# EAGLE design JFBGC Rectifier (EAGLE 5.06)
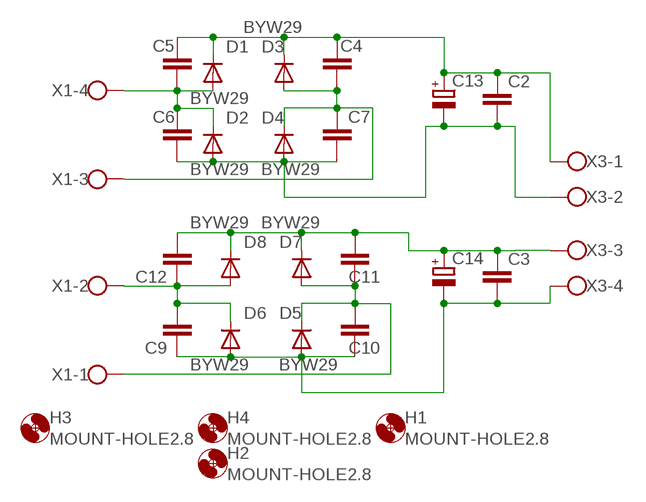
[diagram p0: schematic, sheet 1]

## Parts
C2  C5/3  [C5B3]
C3  C5/3  [C5B3]
C4  C5/3  [C5B3]
C5  C5/3  [C5B3]
C6  C5/3  [C5B3]
C7  C5/3  [C5B3]
C9  C5/3  [C5B3]
C10  C5/3  [C5B3]
C11  C5/3  [C5B3]
C12  C5/3  [C5B3]
C13  CPOL-EUE10-35  [EB35D]
C14  CPOL-EUE10-35  [EB35D]
D1  BYW29  [DO220S]
D2  BYW29  [DO220S]
D3  BYW29  [DO220S]
D4  BYW29  [DO220S]
D5  BYW29  [DO220S]
D6  BYW29  [DO220S]
D7  BYW29  [DO220S]
D8  BYW29  [DO220S]
H1  MOUNT-HOLE2.8  [2,8]
H2  MOUNT-HOLE2.8  [2,8]
H3  MOUNT-HOLE2.8  [2,8]
H4  MOUNT-HOLE2.8  [2,8]
X1  W237-4  [W237-4]
X3  W237-4  [W237-4]

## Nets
N$1: C2.2 C6.2 C7.2 C13.- D2.A D4.A X3.2
N$2: C2.1 C4.2 C5.1 C13.+ D1.C D3.C X3.1
N$3: C5.2 C6.1 D1.A D2.C X1.4
N$4: C3.1 C11.2 C12.2 C14.+ D7.C D8.C X3.3
N$9: C4.1 C7.1 D3.A D4.C X1.3
N$12: C3.2 C9.1 C10.1 C14.- D5.A D6.A X3.4
N$13: C9.2 C12.1 D6.C D8.A X1.2
N$15: C10.2 C11.1 D5.C D7.A X1.1

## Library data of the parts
C2-C7 C9-C12 = capacitor-wima:C: CAPACITOR
C13 C14 = rcl:CPOL-EU: POLARIZED CAPACITOR, European symbol
D1-D8 = diode:BYW29: DIODE
H1-H4 = holes:MOUNT-HOLE: MOUNTING HOLE with drill center marker
X1 X3 = con-wago-500:W237-4: WAGO SCREW CLAMP

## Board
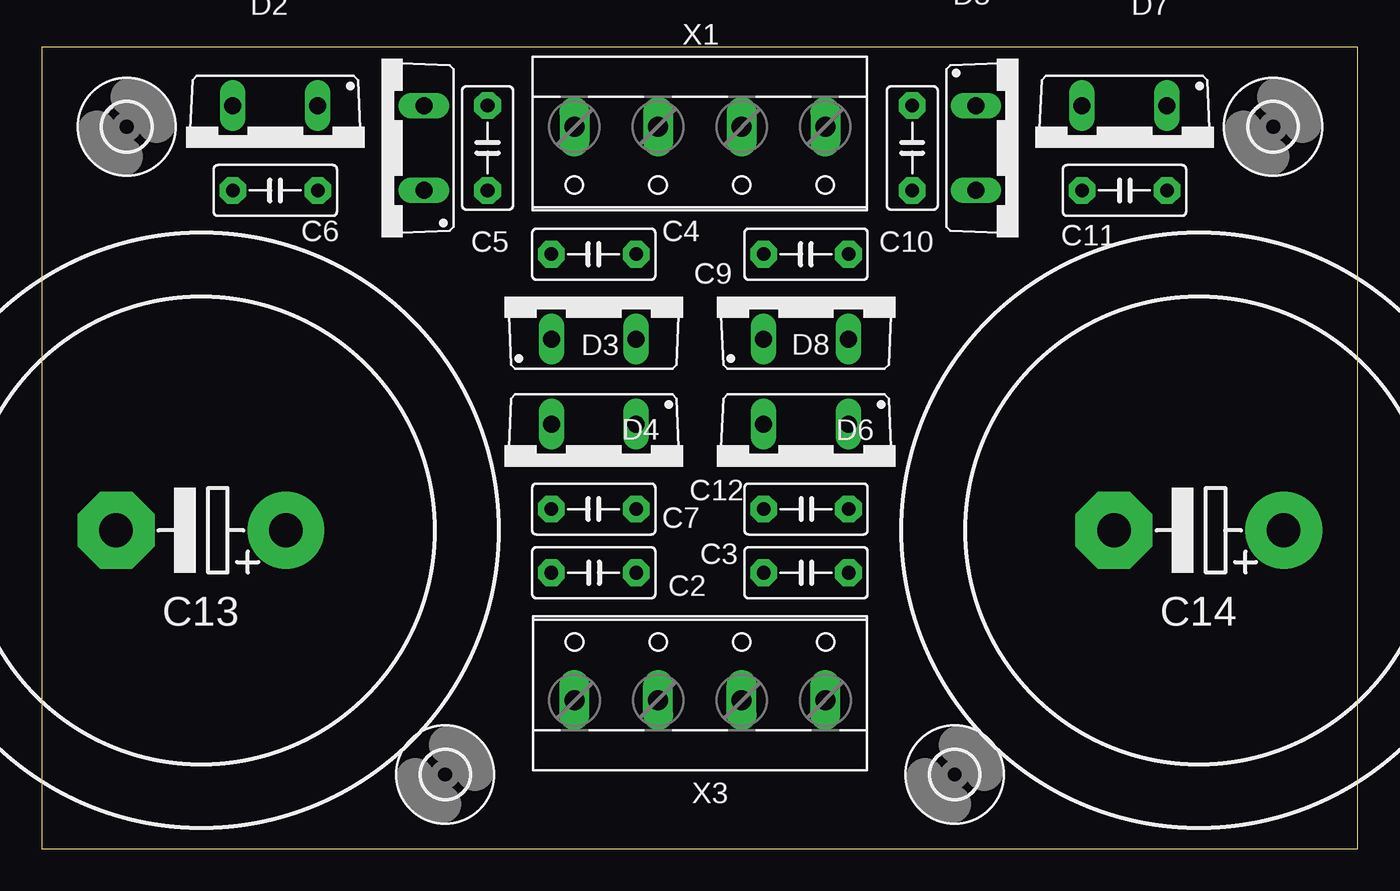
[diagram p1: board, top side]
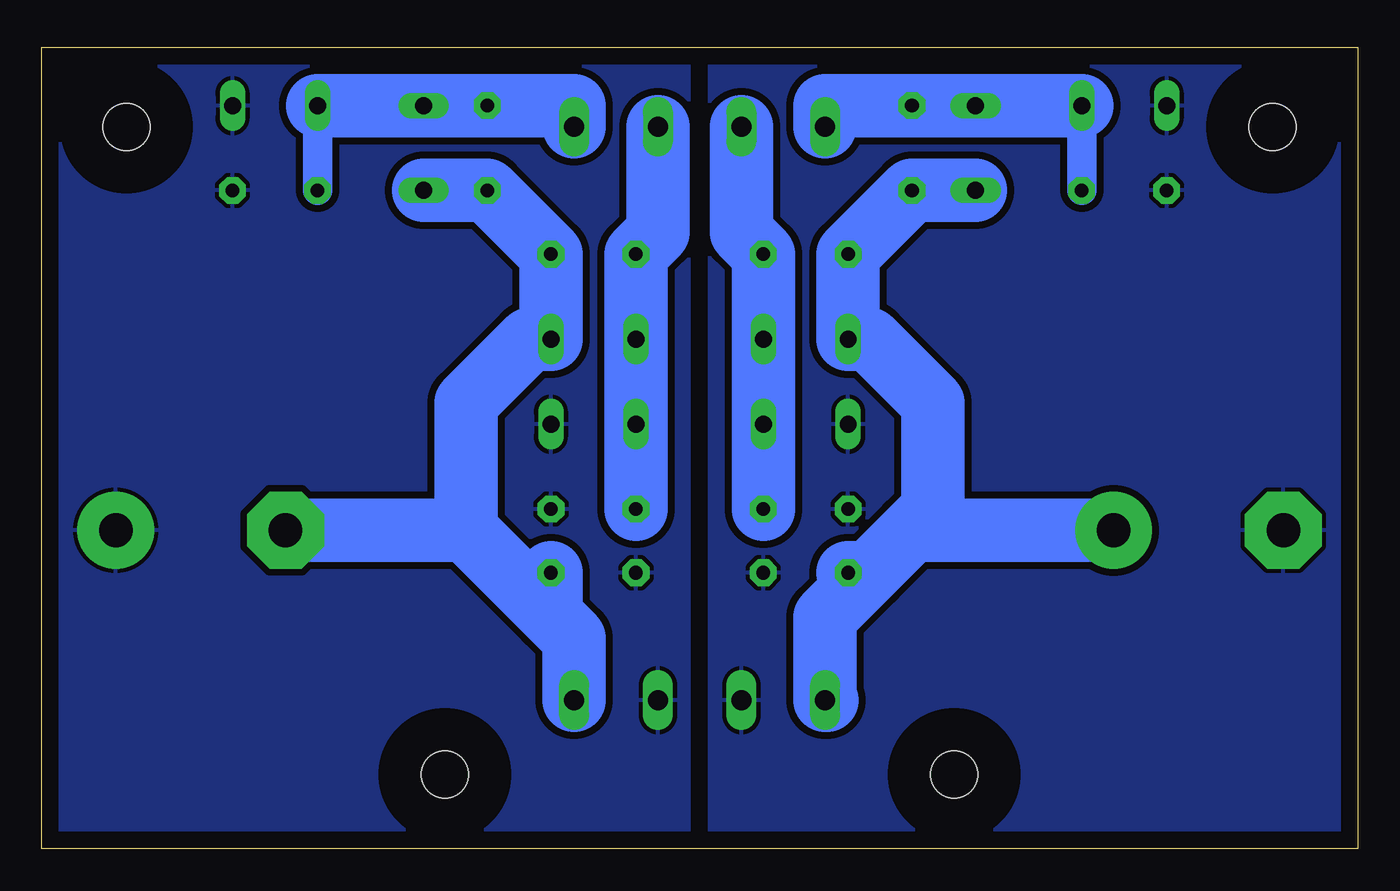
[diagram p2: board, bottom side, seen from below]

Size 78.72 x 47.93 mm. Coordinates in mm from the lower left corner, seen from the top.
Outline: 0,0 78.72,0 78.72,47.93 0,47.93 0,0
Copper layers (1*16): Top 0.035mm / dielectric 1.5mm / Bottom 0.035mm
Design rules "default": minimum track width 10mil, minimum drill 24mil, track to track 8mil, track to pad 8mil, pad to pad 8mil, via to via 8mil, smd to smd 8mil, copper to edge 40mil, drill to drill 8mil, minimum pad ring 10mil, minimum via ring 8mil, stop-mask expansion 4mil, vias tented up to drill 0mil, thermal gap 10mil

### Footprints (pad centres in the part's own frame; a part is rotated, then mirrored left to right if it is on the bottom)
C5B3 = drill 0.813 pad 1.6 octagon: 1 -2.54,0; 2 2.54,0
EB35D = drill 2.007 pad 4.597 round: + -5.08,0 | drill 2.007 pad 4.597 octagon: - 5.08,0
DO220S = drill 1.016 long: A 2.54,-2.54; C -2.54,-2.54
2,8 = hole 2.8: 0,0
W237-4 = drill 1.194 long: 1 -7.5,-1.27; 2 -2.5,-1.27; 3 2.5,-1.27; 4 7.5,-1.27

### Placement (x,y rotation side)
C2  33.02,16.51 0 top
C3  45.72,16.51 0 top
C4  33.02,35.56 180 top
C5  26.67,41.91 90 top
C6  13.97,39.37 180 top
C7  33.02,20.32 180 top
C9  45.72,35.56 180 top
C10  52.07,41.91 90 top
C11  64.77,39.37 0 top
C12  45.72,20.32 0 top
C13  9.52,19.05 180 top
C14  69.22,19.05 180 top
D1  20.32,41.91 90 top
D2  13.97,41.91 180 top
D3  33.02,33.02 0 top
D4  33.02,22.86 180 top
D5  58.42,41.91 270 top
D6  45.72,33.02 0 top
D7  64.77,41.91 180 top
D8  45.72,22.86 180 top
H1  24.13,4.45 0 top
H2  5.08,43.18 0 top
H3  73.66,43.18 0 top
H4  54.61,4.45 0 top
X1  39.37,41.91 180 top
X3  39.37,10.16 0 top

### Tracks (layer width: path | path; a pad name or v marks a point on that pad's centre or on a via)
N$1
  pour Bottom (isolate 0.406): 38.73,48.26 -1.27,48.26 -1.27,-1.27 38.73,-1.27
N$2
  Bottom 3.81: D1.C C5.1 C4.2 D3.C 29.21,30.48 25.4,26.67 25.4,21.59 25.4,20.32 26.67,19.05 | 31.75,8.89 X3.1 31.87,13.85 29.21,16.51 | 26.67,19.05 29.21,16.51 | 29.21,16.51 C2.1 29.21,16.51 | C13.+ 26.67,19.05
N$3
  Bottom 1.778: C6.1 D2.C
  Bottom 3.81: X1.4 31.87,44.45 C5.2 D1.A D2.C
N$4
  pour Bottom (isolate 0.406): 40.01,48.26 80.01,48.26 80.01,-1.27 40.01,-1.27
N$9
  Bottom 3.81: X1.3 36.87,36.87 C4.1 D3.A D4.C C7.1
N$12
  Bottom 3.81: C10.1 D5.A C10.1 | C10.1 C9.1 D6.A 49.53,30.48 53.34,26.67 53.34,21.59 53.34,19.05 | 53.34,19.05 C14.- | X3.4 46.87,12.58 48.26,13.97 | 48.26,13.97 53.34,19.05 | 48.26,13.97 C3.2
N$13
  Bottom 3.81: X1.2 41.87,36.87 C9.2 D6.C D8.A C12.1
N$15
  Bottom 1.778: D7.A C11.1
  Bottom 3.81: X1.1 46.87,44.45 C10.2 D5.C D7.A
